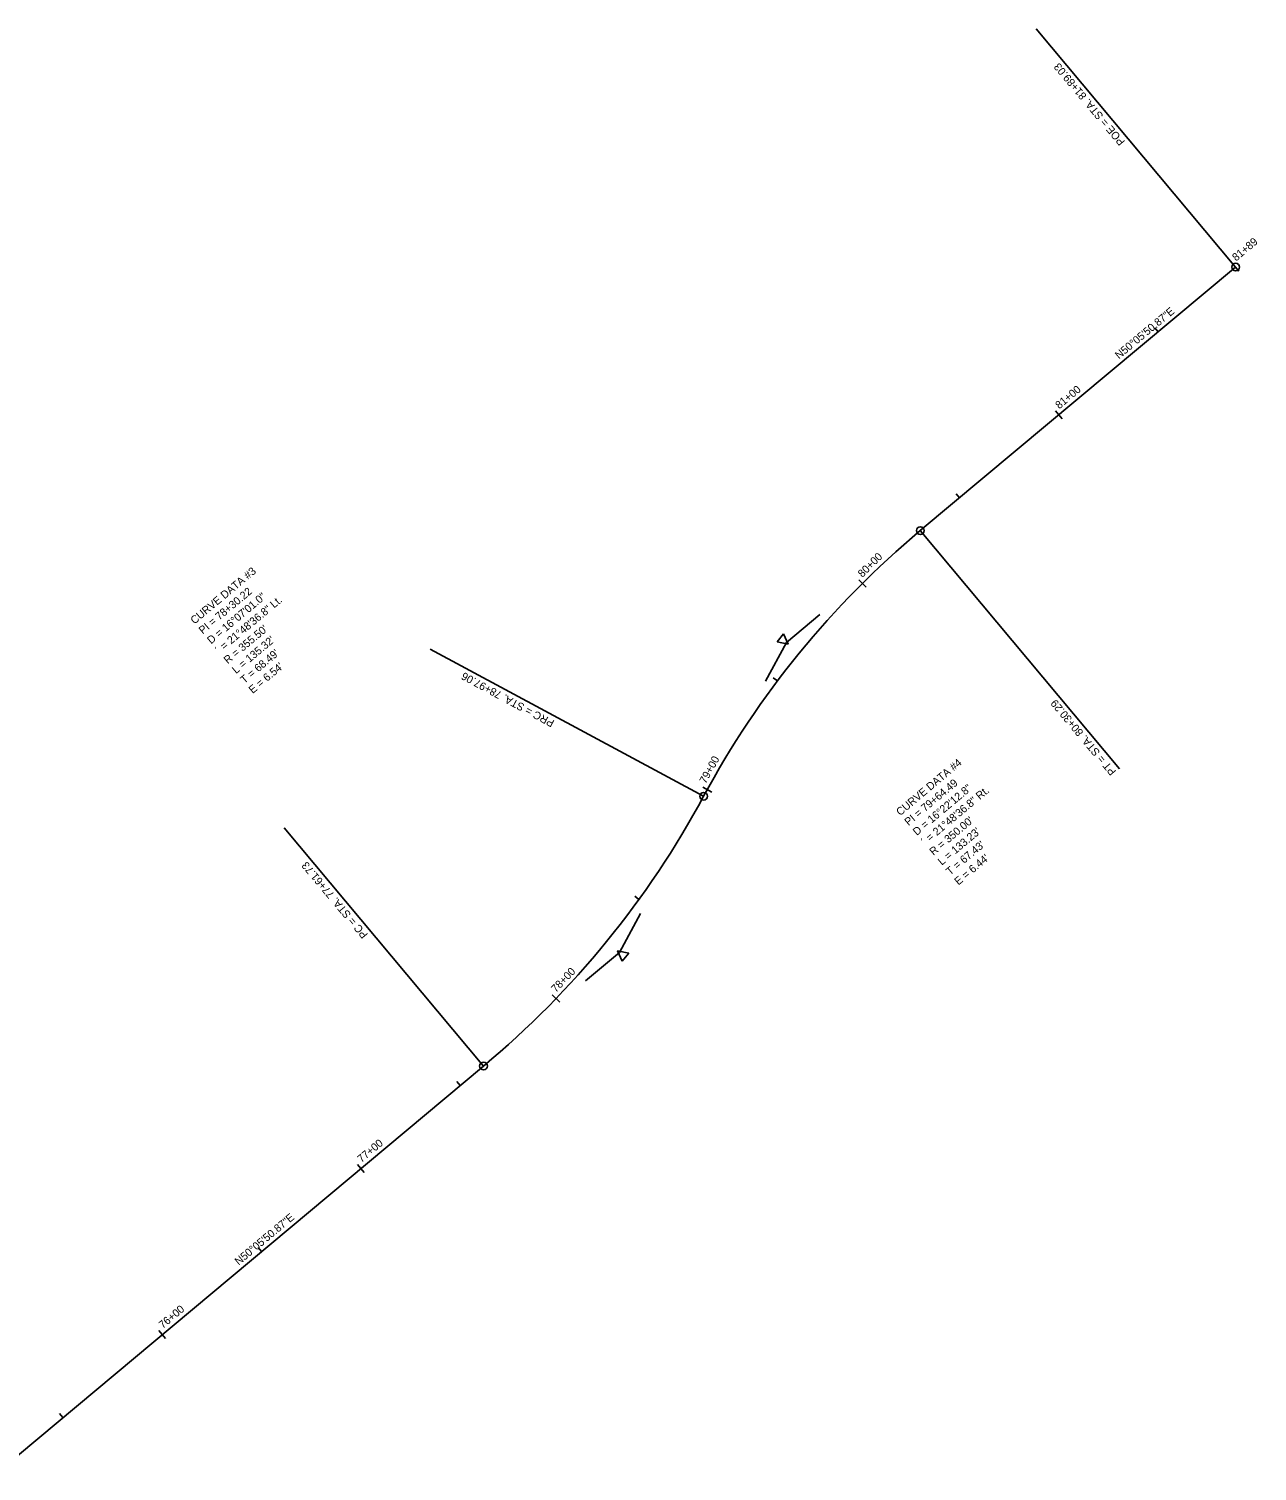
# Model space of a CAD drawing. Extents: x 939026 to 940035, y 627480 to 628252.
# Drawn here: x 939561 to 940035, y 627694 to 628252 of the extents above; entities that cross this region are included whole.
import ezdxf

# ---------------------------------------------------------------- set-up
doc = ezdxf.new("R2010")
doc.units = 0
for name, color, linetype in [('D_Roadway_Centerline', 7, 'Continuous'), ('D_Roadway_Centerline_Bearings', 7, 'Continuous'), ('D_Roadway_Centerline_CurveData', 7, 'Continuous'), ('D_Roadway_Centerline_Flags', 7, 'Continuous'), ('D_Roadway_Centerline_Text', 7, 'Continuous')]:
    doc.layers.add(name, color=color, linetype=linetype)

msp = doc.modelspace()

# ---------------------------------------------------------------- linework, layer by layer
at = {"layer": 'D_Roadway_Centerline'}
for p, q in [((939905.24, 628057.65), (940027.02, 628159.49)), ((939549.37, 627694.24), (939736.56, 627850.77))]:
    msp.add_line(p, q, dxfattribs=at)
for centre, radius, start, end in [((940129.76, 627789.16), 350, 129.9025, 151.7127), ((939508.51, 628123.49), 355.5, 309.9025, 331.7127)]:
    msp.add_arc(centre, radius, start, end, dxfattribs=at)
at = {"layer": 'D_Roadway_Centerline_CurveData'}
for p, q in [((939849.98, 628014.74), (939852.47, 628017.79)), ((939852.47, 628017.79), (939854.27, 628013.78)), ((939854.27, 628013.78), (939849.98, 628014.74)), ((939854.27, 628013.78), (939853.51, 628014.4)), ((939790.14, 627891.32), (939788.33, 627895.33)), ((939788.33, 627895.33), (939792.63, 627894.37)), ((939788.33, 627895.33), (939789.1, 627894.71)), ((939792.63, 627894.37), (939790.14, 627891.32))]:
    msp.add_line(p, q, dxfattribs=at)
for points in [[(939845.52, 627999.55), (939853.51, 628014.4), (939866.44, 628025.21)], [(939775.96, 627883.72), (939789.1, 627894.71), (939797.21, 627909.78)]]:
    msp.add_lwpolyline(points, dxfattribs=at)
at = {"layer": 'D_Roadway_Centerline_Flags'}
for points in [[(940027.02, 628159.49), (939950.04, 628251.54)], [(939905.24, 628057.65), (939982.22, 627965.6)], [(939821.55, 627955.02), (939715.89, 628011.89)], [(939736.56, 627850.77), (939659.58, 627942.83)]]:
    msp.add_lwpolyline(points, dxfattribs=at)
for centre in [(940027.02, 628159.49), (939905.24, 628057.65), (939821.55, 627955.02), (939736.56, 627850.77)]:
    msp.add_circle(centre, 1.5, dxfattribs=at)
at = {"layer": 'D_Roadway_Centerline_Text'}
for points in [[(940025.74, 628161.02), (940028.3, 628157.95)], [(940025.74, 628161.02), (940028.3, 628157.95)], [(939995.79, 628135.98), (939997.08, 628134.45)], [(939957.44, 628103.91), (939960, 628100.84)], [(939919.08, 628071.83), (939920.36, 628070.3)], [(939881.46, 628038.66), (939884.29, 628035.83)], [(939848.47, 628000.77), (939850.07, 627999.57)], [(939821.21, 627958.57), (939824.71, 627956.64)], [(939794.96, 627916.35), (939796.58, 627915.18)], [(939763.1, 627878.24), (939765.98, 627875.46)], [(939726.27, 627844.78), (939727.56, 627843.24)], [(939687.92, 627812.71), (939690.48, 627809.64)], [(939649.56, 627780.63), (939650.84, 627779.1)], [(939611.2, 627748.56), (939613.77, 627745.49)], [(939572.84, 627716.48), (939574.13, 627714.95)]]:
    msp.add_lwpolyline(points, dxfattribs=at)

# ---------------------------------------------------------------- texts
at = {"layer": 'D_Roadway_Centerline_Bearings'}
for p in [(939981.98, 628123.78), (939642, 627773.66)]:
    msp.add_text('N50%%d05\'50.87"E', height=3, rotation=39.9025, dxfattribs=at).set_placement(p)
at = {"layer": 'D_Roadway_Centerline_CurveData'}
for s, p in [('CURVE DATA #3', (939624.91, 628021.33)), ('PI = 78+30.22', (939628.12, 628017.5)), ('D = 16%%d07\'01.0"', (939631.34, 628013.67)), ('´ = 21%%d48\'36.8" Lt.', (939634.55, 628009.83)), ("R = 355.50'", (939637.76, 628006)), ("L = 135.32'", (939640.98, 628002.17)), ("T = 68.49'", (939644.19, 627998.34)), ("E = 6.54'", (939647.4, 627994.51)), ('CURVE DATA #4', (939897.47, 627947.31)), ('PI = 79+64.49', (939900.68, 627943.48)), ('D = 16%%d22\'12.8"', (939903.89, 627939.65)), ('´ = 21%%d48\'36.8" Rt.', (939907.11, 627935.82)), ("R = 350.00'", (939910.32, 627931.99)), ("L = 133.23'", (939913.53, 627928.16)), ("T = 67.43'", (939916.74, 627924.33)), ("E = 6.44'", (939919.96, 627920.49))]:
    msp.add_text(s, height=3, rotation=39.9824, dxfattribs=at).set_placement(p)
at = {"layer": 'D_Roadway_Centerline_Flags'}
for s, rotation, p in [('POE = STA. 81+89.03', 129.9025, (939984.48, 628208.01)), ('PRC = STA. 78+97.06', 151.7127, (939764.2, 627984.18)), ('PT = STA. 80+30.29', 129.9025, (939981.07, 627964.64)), ('PC = STA. 77+61.73', 129.9025, (939692.08, 627901.62))]:
    msp.add_text(s, height=3, rotation=rotation, dxfattribs=at).set_placement(p)
at = {"layer": 'D_Roadway_Centerline_Text'}
for s, rotation, p in [('81+89', 39.9025, (940027.21, 628161.6)), ('81+89', 39.9025, (940027.21, 628161.6)), ('81+00', 39.9025, (939958.91, 628104.49)), ('80+00', 44.8606, (939882.88, 628039.37)), ('79+00', 61.2309, (939822.37, 627959.64)), ('78+00', 46.0702, (939764.5, 627878.97)), ('77+00', 39.9025, (939689.39, 627813.28)), ('76+00', 39.9025, (939612.67, 627749.14))]:
    msp.add_text(s, height=3, rotation=rotation, dxfattribs=at).set_placement(p)

doc.saveas('drawing.dxf')
